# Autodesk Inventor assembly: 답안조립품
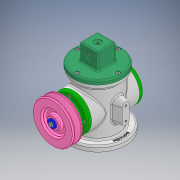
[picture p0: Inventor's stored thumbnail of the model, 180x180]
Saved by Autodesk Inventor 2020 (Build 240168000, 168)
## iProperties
Created: 2023-02
Part Number: 답안조립품
Document SubType Name: Assembly
Designer: com
Author: com
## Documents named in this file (18)
- C:\Users\com\Desktop\730206V1003\답안조립품.iam
- C:\Users\com\Desktop\730206V1003\본체.ipt
- C:\Users\com\Desktop\730206V1003\공용부품\뒤커버.ipt
- C:\Users\com\Desktop\730206V1003\공용부품\베어링 17 x 40 x 12.ipt
- C:\Users\com\Desktop\730206V1003\공용부품\앞커버.ipt
- C:\Users\com\Desktop\730206V1003\공용부품\오일 실 17 30 8.ipt
- C:\Users\com\Desktop\730206V1003\공용부품\편심축.ipt
- C:\Users\com\Desktop\730206V1003\공용부품\V-벨트풀리.ipt
- C:\Users\com\Desktop\730206V1003\공용부품\볼트 M4 x 10.ipt
- C:\Users\com\Desktop\730206V1003\공용부품\와셔 4x16.ipt
- C:\Users\com\Desktop\730206V1003\공용부품\키 4 x 4 x 12.ipt
- C:\Users\com\Desktop\730206V1003\공용부품\링크.ipt
- C:\Users\com\Desktop\730206V1003\공용부품\슬라이더.ipt
- C:\Users\com\Desktop\730206V1003\공용부품\클레비스 핀 6 x 22.ipt
- 클레비스 핀 6 x 22.ipt
- C:\Users\com\Desktop\730206V1003\공용부품\E-링.ipt
- C:\Users\com\Desktop\730206V1003\공용부품\덮개.ipt
- C:\Users\com\Desktop\730206V1003\공용부품\볼트 M4 x 8.ipt
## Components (2 placed, 2 different names)
1. V-벨트풀리:1
2. E-링:1
